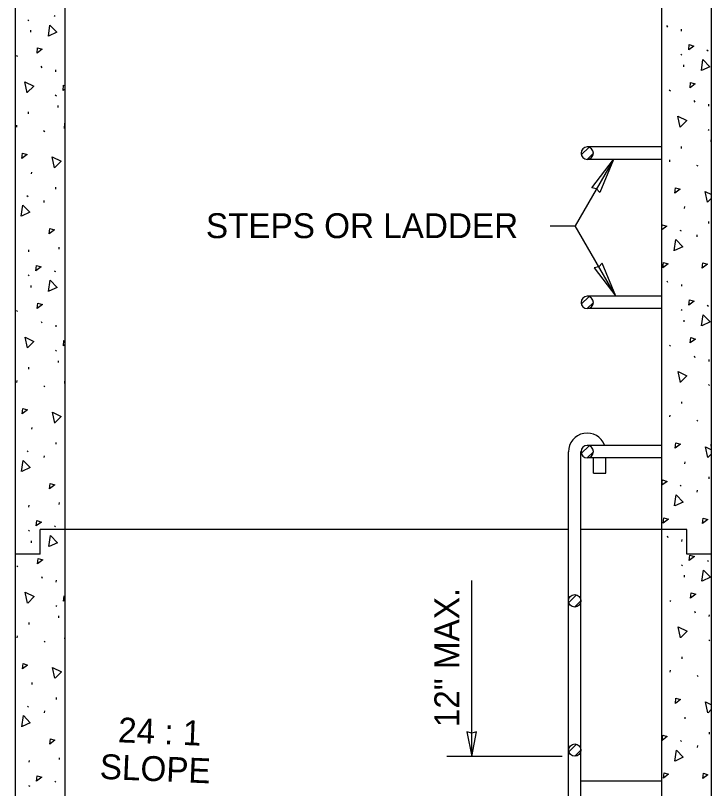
# Model space of a CAD drawing. Extents: x 99862 to 104211, y 98939 to 102076.
# Drawn here: x 100813.2 to 101261.2, y 100517.1 to 101014.4 of the extents above; entities that cross this region are included whole.
import ezdxf

# ---------------------------------------------------------------- set-up
doc = ezdxf.new("R2010")
doc.units = 0
for name, color, linetype in [('Level 15', 7, 'Continuous'), ('Level 17', 7, 'Continuous'), ('Level 18', 7, 'Continuous'), ('Level 19', 7, 'Continuous'), ('Level 20', 7, 'Continuous')]:
    doc.layers.add(name, color=color, linetype=linetype)

msp = doc.modelspace()

# ---------------------------------------------------------------- linework, layer by layer
at = {"layer": 'Level 15'}
for p, q in [((101198.08, 100921.79), (101173.46, 100879.15)), ((101157.46, 100879.15), (101173.46, 100879.15)), ((101199.65, 100833.79), (101173.46, 100879.15)), ((101106.84, 100537.75), (101106.84, 100650.96)), ((101165.03, 100537.75), (101090.84, 100537.75))]:
    msp.add_line(p, q, dxfattribs=at)
for points in [[(101198.08, 100921.79), (101189.25, 100900.53), (101187.19, 100902.93), (101184.08, 100903.51)], [(101199.65, 100833.79), (101190.82, 100855.05), (101188.76, 100852.65), (101185.65, 100852.07)], [(101106.84, 100537.75), (101109.92, 100553.47), (101106.84, 100552.75), (101103.75, 100553.47)]]:
    msp.add_lwpolyline(points, close=True, dxfattribs=at)
at = {"layer": 'Level 17'}
for p, q in [((101229.22, 100299.79), (101229.22, 101853.53)), ((101261.22, 100251.79), (101261.22, 101853.53)), ((100813.22, 100251.79), (100813.22, 101461.47)), ((100845.22, 100299.79), (100845.22, 101451.79)), ((100829.22, 100667.79), (100829.22, 100683.79)), ((100845.22, 100683.79), (100829.22, 100683.79)), ((101169.16, 100683.79), (100845.22, 100683.79)), ((101229.22, 100683.79), (101177.16, 100683.79)), ((101245.22, 100683.79), (101229.22, 100683.79)), ((101245.22, 100667.79), (101245.22, 100683.79)), ((100829.22, 100667.79), (100813.22, 100667.79)), ((101261.22, 100667.79), (101245.22, 100667.79))]:
    msp.add_line(p, q, dxfattribs=at)
at = {"layer": 'Level 18'}
for p, q in [((101177.38, 100924.66), (101182.36, 100929.62)), ((101229.22, 100929.79), (101181.22, 100929.79)), ((101181.21, 100921.79), (101185.21, 100925.78)), ((101229.22, 100921.79), (101181.22, 100921.79)), ((101177.38, 100828.66), (101182.36, 100833.62)), ((101229.22, 100833.79), (101181.22, 100833.79)), ((101181.21, 100825.79), (101185.21, 100829.78)), ((101229.22, 100825.79), (101181.22, 100825.79)), ((101177.38, 100732.66), (101182.36, 100737.62)), ((101229.22, 100737.79), (101181.22, 100737.79)), ((101169.16, 100489.69), (101169.16, 100733.68)), ((101177.16, 100490.02), (101177.16, 100733.85)), ((101181.21, 100729.79), (101185.21, 100733.78)), ((101229.22, 100729.79), (101181.22, 100729.79)), ((101185.16, 100719.9), (101185.16, 100729.79)), ((101193.16, 100719.9), (101193.16, 100729.79)), ((101185.16, 100719.9), (101193.16, 100719.9)), ((101169.29, 100636.67), (101174.27, 100641.63)), ((101173.12, 100633.8), (101177.13, 100637.79)), ((101169.34, 100540.67), (101174.32, 100545.63)), ((101173.17, 100537.8), (101177.18, 100541.79)), ((101229.22, 100521.79), (101177.16, 100521.79))]:
    msp.add_line(p, q, dxfattribs=at)
for centre in [(101173.13, 100637.8), (101173.18, 100541.8)]:
    msp.add_circle(centre, 4, dxfattribs=at)
for centre, radius, start, end in [((101181.21, 100925.79), 4, 270, 269.93), ((101181.21, 100829.79), 4, 270, 269.93), ((101181.16, 100733.75), 12, 20.5013, 180.3346), ((101181.21, 100733.79), 4, 270, 269.93)]:
    msp.add_arc(centre, radius, start, end, dxfattribs=at)
at = {"layer": 'Level 19'}
for p, q in [((100838.03, 101014.4), (100838.75, 101013.87)), ((100821.21, 101011.65), (100821.93, 101011.12)), ((100823.13, 101003.63), (100823.22, 101004.85)), ((101232.29, 101007.95), (101232.79, 101006.94)), ((101241.84, 101004.4), (101241.92, 101005.62)), ((101241.47, 100989.45), (101242.19, 100988.92)), ((101258.29, 100992.2), (101259.01, 100991.67)), ((100813.74, 100988.7), (100814.46, 100988.17)), ((100829.63, 100981.79), (100830.13, 100980.78)), ((100839.17, 100978.24), (100839.26, 100979.47)), ((101243.39, 100981.43), (101243.47, 100982.65)), ((101234, 100966.5), (101234.72, 100965.97)), ((100838.81, 100963.3), (100839.53, 100962.77)), ((101249.89, 100959.6), (101250.39, 100958.59)), ((100840.73, 100955.28), (100840.81, 100956.5)), ((101259.43, 100956.05), (101259.52, 100957.27)), ((100821.61, 100951.08), (100821.7, 100952.31)), ((100814.02, 100942.51), (100814.1, 100943.74)), ((100831.34, 100940.35), (100832.06, 100939.82)), ((101259.07, 100941.1), (101259.79, 100940.57)), ((101260.99, 100933.08), (101261.07, 100934.3)), ((101241.87, 100928.89), (101241.96, 100930.11)), ((101234.28, 100920.32), (101234.36, 100921.54)), ((101251.6, 100918.15), (101252.32, 100917.63)), ((100823.65, 100912.42), (100823.73, 100913.64)), ((100839.21, 100902.73), (100839.3, 100903.96)), ((100820.6, 100898.55), (100821.32, 100898.02)), ((100831.62, 100894.16), (100831.7, 100895.39)), ((101243.91, 100890.22), (101243.99, 100891.44)), ((101259.47, 100880.54), (101259.56, 100881.76)), ((101240.86, 100876.35), (101241.58, 100875.82)), ((101251.87, 100871.97), (101251.96, 100873.19)), ((100841.25, 100864.07), (100841.33, 100865.29)), ((100821.75, 100862.39), (100821.83, 100863.61)), ((100838.2, 100850.2), (100838.92, 100849.67)), ((100821.38, 100847.45), (100822.1, 100846.92)), ((100823.3, 100839.43), (100823.39, 100840.65)), ((101232.46, 100843.75), (101232.96, 100842.74)), ((101242.01, 100840.2), (101242.09, 100841.42)), ((101241.64, 100825.25), (101242.36, 100824.72)), ((101258.46, 100828), (101259.18, 100827.47)), ((100813.91, 100824.5), (100814.63, 100823.97)), ((100829.8, 100817.59), (100830.3, 100816.58)), ((100839.34, 100814.04), (100839.43, 100815.27)), ((101243.56, 100817.23), (101243.64, 100818.45)), ((101234.17, 100802.3), (101234.89, 100801.77)), ((100838.98, 100799.1), (100839.7, 100798.57)), ((101250.06, 100795.4), (101250.56, 100794.39)), ((100840.9, 100791.08), (100840.98, 100792.3)), ((101259.6, 100791.85), (101259.69, 100793.07)), ((100821.78, 100786.88), (100821.87, 100788.11)), ((100814.19, 100778.31), (100814.27, 100779.53)), ((100831.51, 100776.15), (100832.23, 100775.62)), ((101259.24, 100776.9), (101259.96, 100776.37)), ((101242.04, 100764.69), (101242.13, 100765.91)), ((101261.16, 100768.88), (101261.22, 100769.76)), ((101234.45, 100756.12), (101234.53, 100757.34)), ((101251.77, 100753.95), (101252.49, 100753.43)), ((100823.82, 100748.22), (100823.91, 100749.44)), ((100839.38, 100738.53), (100839.47, 100739.76)), ((100820.77, 100734.35), (100821.49, 100733.82)), ((100831.79, 100729.96), (100831.87, 100731.19)), ((101244.08, 100726.02), (101244.16, 100727.24)), ((101259.64, 100716.34), (101259.73, 100717.56)), ((101241.03, 100712.15), (101241.75, 100711.62)), ((101252.04, 100707.77), (101252.13, 100708.99)), ((100841.42, 100699.87), (100841.5, 100701.09)), ((100821.92, 100698.19), (100822, 100699.41)), ((100838.37, 100686), (100839.09, 100685.47)), ((100821.55, 100683.25), (100822.27, 100682.72)), ((100823.47, 100675.23), (100823.56, 100676.45)), ((101232.63, 100679.55), (101233.13, 100678.54)), ((101242.18, 100676), (101242.26, 100677.22)), ((101241.81, 100661.05), (101242.53, 100660.52)), ((101258.63, 100663.8), (101259.35, 100663.27)), ((100814.08, 100660.3), (100814.8, 100659.77)), ((100829.97, 100653.39), (100830.47, 100652.38)), ((100839.51, 100649.84), (100839.6, 100651.07)), ((101243.73, 100653.03), (101243.81, 100654.25)), ((101234.34, 100638.1), (101235.06, 100637.57)), ((100839.15, 100634.9), (100839.87, 100634.37)), ((101250.23, 100631.2), (101250.73, 100630.19)), ((100841.07, 100626.88), (100841.15, 100628.1)), ((101259.77, 100627.65), (101259.86, 100628.87)), ((100821.95, 100622.68), (100822.04, 100623.91)), ((100814.36, 100614.11), (100814.44, 100615.33)), ((100831.68, 100611.95), (100832.4, 100611.42)), ((101259.41, 100612.7), (101260.13, 100612.17)), ((101242.21, 100600.49), (101242.3, 100601.71)), ((101234.62, 100591.92), (101234.7, 100593.14)), ((101251.94, 100589.75), (101252.66, 100589.22)), ((100823.99, 100584.02), (100824.08, 100585.24)), ((100839.55, 100574.33), (100839.64, 100575.56)), ((100820.94, 100570.15), (100821.66, 100569.62)), ((100831.96, 100565.76), (100832.04, 100566.99)), ((101244.25, 100561.82), (101244.33, 100563.04)), ((101259.81, 100552.14), (101259.9, 100553.36)), ((101241.2, 100547.95), (101241.92, 100547.42)), ((101252.21, 100543.57), (101252.3, 100544.79)), ((100841.59, 100535.67), (100841.67, 100536.89)), ((100822.09, 100533.99), (100822.17, 100535.21)), ((100838.54, 100521.8), (100839.26, 100521.27)), ((100821.72, 100519.05), (100822.44, 100518.52))]:
    msp.add_line(p, q, dxfattribs=at)
for points in [[(100834.42, 101001.12), (100835.4, 101008.23), (100839.86, 101003.63), (100834.53, 101001.17)], [(101246.53, 100992.22), (101246.87, 100995.65), (101249.85, 100994.75), (101246.53, 100992.22)], [(100827.12, 100990.13), (100827.45, 100993.56), (100830.43, 100992.66), (100827.12, 100990.13)], [(101254.68, 100978.93), (101255.66, 100986.03), (101260.11, 100981.44), (101254.79, 100978.97)], [(100820.7, 100964.73), (100819.2, 100971.74), (100824.96, 100968.94), (100820.8, 100964.81)], [(100843.87, 100966.06), (100844.21, 100969.49), (100845.22, 100969.19)], [(101247.38, 100967.93), (101247.71, 100971.36), (101250.69, 100970.46), (101247.38, 100967.93)], [(100845.22, 100967.09), (100843.87, 100966.06)], [(101240.96, 100942.53), (101239.46, 100949.55), (101245.22, 100946.75), (101241.06, 100942.61)], [(100844.72, 100941.78), (100845.05, 100945.21), (100845.22, 100945.16)], [(100845.22, 100942.16), (100844.72, 100941.78)], [(100817.4, 100922.38), (100817.74, 100925.81), (100820.71, 100924.91), (100817.4, 100922.38)], [(100838.3, 100916.38), (100836.8, 100923.4), (100842.55, 100920.6), (100838.4, 100916.46)], [(101237.66, 100900.18), (101238, 100903.61), (101240.97, 100902.71), (101237.66, 100900.18)], [(101258.56, 100894.19), (101257.06, 100901.2), (101261.22, 100899.17)], [(101261.22, 100896.81), (101258.66, 100894.26)], [(100816.99, 100885.27), (100817.98, 100892.38), (100822.43, 100887.78), (100817.11, 100885.32)], [(101229.22, 100877.51), (101229.44, 100879.8), (101232.42, 100878.89), (101229.22, 100876.45)], [(100835, 100874.03), (100835.34, 100877.46), (100838.31, 100876.56), (100835, 100874.03)], [(101237.25, 100863.08), (101238.24, 100870.18), (101242.69, 100865.58), (101237.37, 100863.12)], [(101229.95, 100852.08), (101230.28, 100855.51), (101233.26, 100854.61), (101229.95, 100852.08)], [(101255.26, 100851.83), (101255.6, 100855.27), (101258.57, 100854.36), (101255.26, 100851.83)], [(100826.44, 100850.21), (100826.78, 100853.64), (100829.76, 100852.74), (100826.44, 100850.21)], [(100834.59, 100836.92), (100835.57, 100844.03), (100840.03, 100839.43), (100834.7, 100836.97)], [(101246.7, 100828.02), (101247.04, 100831.45), (101250.02, 100830.55), (101246.7, 100828.02)], [(100827.29, 100825.93), (100827.62, 100829.36), (100830.6, 100828.46), (100827.29, 100825.93)], [(101254.85, 100814.73), (101255.83, 100821.83), (101260.28, 100817.23), (101254.96, 100814.77)], [(100820.87, 100800.53), (100819.37, 100807.54), (100825.13, 100804.74), (100820.97, 100800.61)], [(100844.04, 100801.86), (100844.38, 100805.29), (100845.22, 100805.04)], [(101247.55, 100803.73), (101247.88, 100807.16), (101250.86, 100806.26), (101247.55, 100803.73)], [(100845.22, 100802.76), (100844.04, 100801.86)], [(101241.13, 100778.33), (101239.63, 100785.35), (101245.39, 100782.55), (101241.23, 100778.41)], [(100844.89, 100777.58), (100845.22, 100780.98)], [(100845.22, 100777.83), (100844.89, 100777.58)], [(100817.57, 100758.18), (100817.91, 100761.61), (100820.88, 100760.71), (100817.57, 100758.18)], [(100838.47, 100752.18), (100836.97, 100759.2), (100842.72, 100756.4), (100838.57, 100752.26)], [(101237.83, 100735.98), (101238.17, 100739.41), (101241.14, 100738.51), (101237.83, 100735.98)], [(101258.73, 100729.98), (101257.23, 100737), (101261.22, 100735.06)], [(101260.94, 100737.25), (101261.22, 100740.05)], [(101261.22, 100737.46), (101260.94, 100737.25)], [(101261.22, 100732.44), (101258.83, 100730.06)], [(100817.16, 100721.07), (100818.15, 100728.18), (100822.6, 100723.58), (100817.28, 100721.12)], [(101229.27, 100712.16), (101229.61, 100715.6), (101232.59, 100714.69), (101229.27, 100712.16)], [(100835.17, 100709.83), (100835.51, 100713.26), (100838.48, 100712.36), (100835.17, 100709.83)], [(101237.42, 100698.88), (101238.41, 100705.98), (101242.86, 100701.38), (101237.54, 100698.92)], [(101230.12, 100687.88), (101230.45, 100691.31), (101233.43, 100690.41), (101230.12, 100687.88)], [(101255.43, 100687.63), (101255.77, 100691.07), (101258.74, 100690.16), (101255.43, 100687.63)], [(100826.61, 100686.01), (100826.95, 100689.44), (100829.93, 100688.54), (100826.61, 100686.01)], [(100834.76, 100672.72), (100835.74, 100679.83), (100840.2, 100675.23), (100834.87, 100672.77)], [(101229.22, 100672.28), (101229.23, 100672.28), (101229.22, 100672.27)], [(101246.87, 100663.82), (101247.21, 100667.25), (101250.19, 100666.35), (101246.87, 100663.82)], [(100827.46, 100661.73), (100827.79, 100665.16), (100830.77, 100664.26), (100827.46, 100661.73)], [(101255.02, 100650.53), (101256, 100657.63), (101260.45, 100653.03), (101255.13, 100650.57)], [(100821.04, 100636.33), (100819.54, 100643.34), (100825.3, 100640.54), (100821.14, 100636.41)], [(100844.21, 100637.66), (100844.55, 100641.09), (100845.22, 100640.89)], [(101247.72, 100639.53), (101248.05, 100642.96), (101251.03, 100642.06), (101247.72, 100639.53)], [(100845.22, 100638.43), (100844.21, 100637.66)], [(101241.3, 100614.13), (101239.8, 100621.15), (101245.56, 100618.35), (101241.4, 100614.21)], [(100845.06, 100613.38), (100845.22, 100615.04)], [(100845.22, 100613.5), (100845.06, 100613.38)], [(100817.74, 100593.98), (100818.08, 100597.41), (100821.05, 100596.51), (100817.74, 100593.98)], [(100838.64, 100587.98), (100837.14, 100594.99), (100842.89, 100592.19), (100838.74, 100588.06)], [(101238, 100571.78), (101238.34, 100575.21), (101241.31, 100574.31), (101238, 100571.78)], [(101258.9, 100565.78), (101257.4, 100572.8), (101261.22, 100570.94)], [(101261.11, 100573.05), (101261.22, 100574.11)], [(101261.22, 100573.13), (101261.11, 100573.05)], [(101261.22, 100568.07), (101259, 100565.86)], [(100817.33, 100556.87), (100818.32, 100563.97), (100822.77, 100559.38), (100817.45, 100556.92)], [(101229.44, 100547.96), (101229.78, 100551.39), (101232.76, 100550.49), (101229.44, 100547.96)], [(100813.22, 100548.44), (100813.34, 100548.41), (100813.22, 100548.31)], [(100835.34, 100545.63), (100835.68, 100549.06), (100838.65, 100548.16), (100835.34, 100545.63)], [(101237.59, 100534.68), (101238.58, 100541.78), (101243.03, 100537.18), (101237.71, 100534.72)], [(101230.29, 100523.68), (101230.62, 100527.11), (101233.6, 100526.21), (101230.29, 100523.68)], [(101255.6, 100523.43), (101255.94, 100526.87), (101258.91, 100525.96), (101255.6, 100523.43)], [(100826.78, 100521.81), (100827.12, 100525.24), (100830.1, 100524.34), (100826.78, 100521.81)]]:
    msp.add_lwpolyline(points, dxfattribs=at)

# ---------------------------------------------------------------- texts
at = {"layer": 'Level 20'}
msp.add_text('STEPS OR LADDER', height=16, dxfattribs=at).set_placement((100935.8, 100871.15))
for s, rotation, p in [('12" MAX.', 90, (101098.84, 100556.56)), ('24 : 1', 357.62, (100879.01, 100546.87)), ('SLOPE', 357.62, (100867.24, 100523.34))]:
    msp.add_text(s, height=16, rotation=rotation, dxfattribs=at).set_placement(p)

doc.saveas('drawing.dxf')
